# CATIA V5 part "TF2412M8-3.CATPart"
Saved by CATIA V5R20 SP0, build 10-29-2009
Part number: TF2412M8-3
Revision: ANY
Definition: UNKNOWN
Nomenclature: TF2412M8-3
Source: Unknown
Bounding box of the stored display mesh (mm): x -5.703 to 5.703, y 0 to 4.55, z -5.85 to 5.85
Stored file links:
  C:\Users\Utente\Desktop\IO LAVORO\3D X SITO CF\CUMSA\3D files RCM\RCM 245712\TF2412M8-3.CATPart
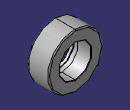
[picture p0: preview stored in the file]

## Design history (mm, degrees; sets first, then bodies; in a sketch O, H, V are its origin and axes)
Body1 "Cortar-Revolución1" (main body)
  Solid1: solid without history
